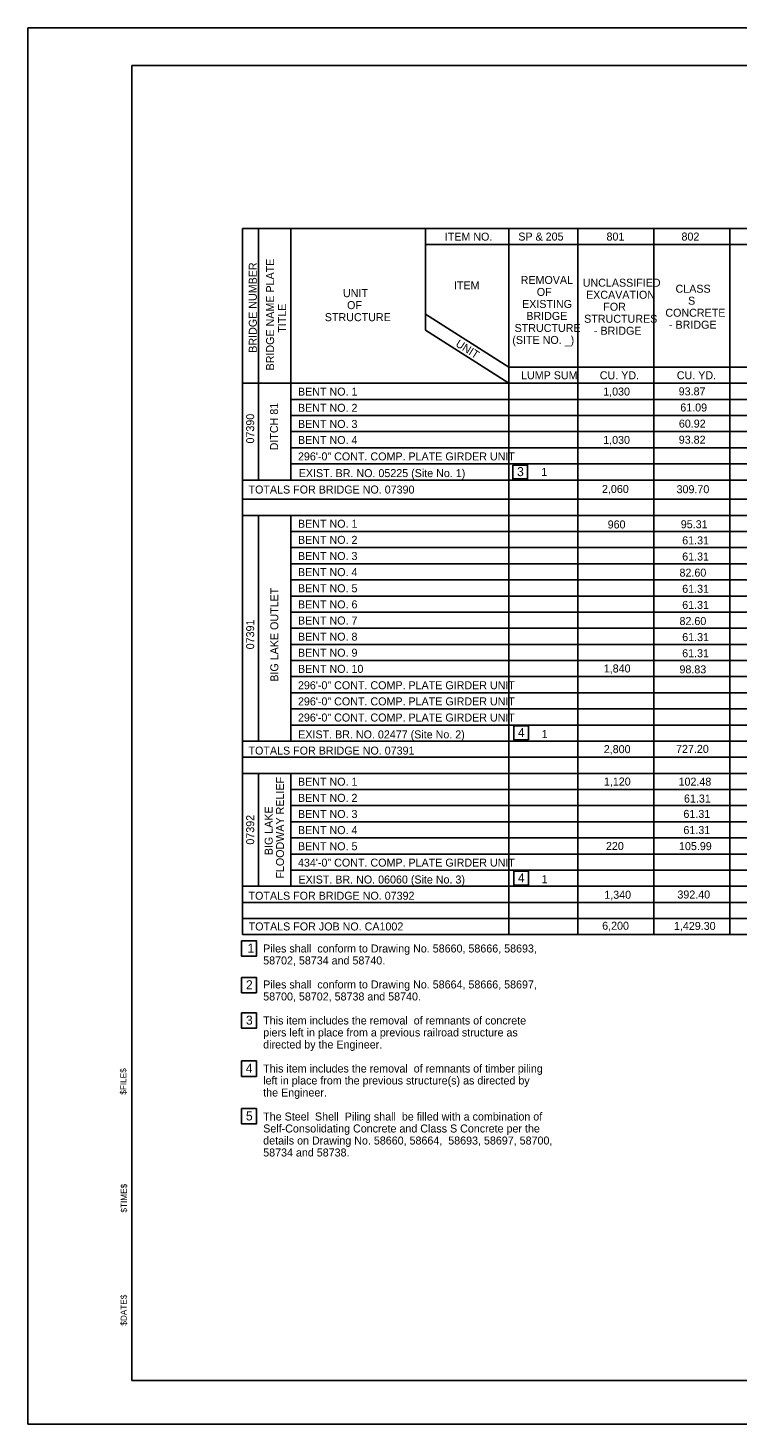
# Model space of a CAD drawing. Extents: x 117751.5 to 117785.6, y 28052.1 to 28074.
# Drawn here: x 117751.53 to 117762.6, y 28052.15 to 28073.96 of the extents above; entities that cross this region are included whole.
import ezdxf

# ---------------------------------------------------------------- set-up
doc = ezdxf.new("R2010")
doc.units = 0
for name, color, linetype in [('border', 7, 'Continuous'), ('Level 1', 7, 'Continuous'), ('Level 40', 7, 'Continuous'), ('Level 62', 7, 'Continuous')]:
    doc.layers.add(name, color=color, linetype=linetype)

msp = doc.modelspace()

# ---------------------------------------------------------------- linework, layer by layer
at = {"layer": 'border'}
for p, q in [((117753.15, 28073.371), (117785.161, 28073.371)), ((117753.15, 28052.826), (117753.15, 28073.371)), ((117785.161, 28052.826), (117753.15, 28052.826))]:
    msp.add_line(p, q, dxfattribs=at)
at = {"layer": 'Level 1'}
for p, q in [((117754.881, 28070.823), (117754.881, 28059.793)), ((117754.881, 28070.823), (117783.697, 28070.823)), ((117755.133, 28070.823), (117755.133, 28066.894)), ((117755.637, 28070.823), (117755.637, 28066.894)), ((117757.737, 28070.824), (117757.737, 28069.235)), ((117759.038, 28059.793), (117759.038, 28070.823)), ((117760.12, 28059.793), (117760.12, 28070.823)), ((117761.307, 28059.793), (117761.307, 28070.823)), ((117762.493, 28059.793), (117762.493, 28070.823)), ((117757.737, 28070.571), (117773.657, 28070.571)), ((117757.737, 28069.487), (117759.038, 28068.657)), ((117757.737, 28069.235), (117759.038, 28068.405)), ((117759.038, 28068.657), (117783.697, 28068.657)), ((117754.881, 28068.405), (117783.697, 28068.405)), ((117755.637, 28068.153), (117783.697, 28068.153)), ((117755.637, 28067.901), (117783.697, 28067.901)), ((117755.637, 28067.65), (117783.697, 28067.649)), ((117755.637, 28067.398), (117783.697, 28067.398)), ((117755.637, 28067.146), (117783.697, 28067.146)), ((117754.881, 28066.894), (117783.697, 28066.894)), ((117754.881, 28066.593), (117783.697, 28066.593)), ((117754.881, 28066.342), (117783.697, 28066.342)), ((117755.133, 28062.815), (117755.133, 28066.342)), ((117755.637, 28062.815), (117755.637, 28066.342)), ((117755.637, 28066.09), (117783.697, 28066.09)), ((117755.637, 28065.838), (117783.697, 28065.838)), ((117755.637, 28065.586), (117783.697, 28065.586)), ((117755.637, 28065.334), (117783.697, 28065.334)), ((117755.637, 28065.082), (117783.697, 28065.082)), ((117755.637, 28064.83), (117783.697, 28064.83)), ((117755.637, 28064.578), (117783.697, 28064.578)), ((117755.637, 28064.327), (117783.697, 28064.327)), ((117755.637, 28064.075), (117783.697, 28064.075)), ((117755.637, 28063.823), (117783.697, 28063.823)), ((117755.637, 28063.571), (117783.697, 28063.571)), ((117755.637, 28063.319), (117783.697, 28063.319)), ((117755.637, 28063.067), (117783.697, 28063.067)), ((117754.881, 28062.815), (117783.697, 28062.815)), ((117754.881, 28062.563), (117773.657, 28062.563)), ((117754.881, 28062.563), (117783.697, 28062.563)), ((117754.881, 28062.312), (117783.697, 28062.312)), ((117755.133, 28060.548), (117755.133, 28062.312)), ((117755.637, 28060.548), (117755.637, 28062.312)), ((117755.637, 28062.06), (117783.697, 28062.06)), ((117755.637, 28061.808), (117783.697, 28061.808)), ((117755.637, 28061.556), (117783.697, 28061.556)), ((117755.637, 28061.304), (117783.697, 28061.304)), ((117755.637, 28061.052), (117783.697, 28061.052)), ((117755.637, 28060.8), (117783.697, 28060.8)), ((117754.881, 28060.548), (117783.697, 28060.548)), ((117754.881, 28060.297), (117773.657, 28060.297)), ((117754.881, 28060.297), (117783.697, 28060.297)), ((117754.881, 28060.045), (117773.657, 28060.045)), ((117754.881, 28060.045), (117783.697, 28060.045)), ((117754.881, 28059.793), (117773.657, 28059.793)), ((117754.881, 28059.793), (117783.697, 28059.793))]:
    msp.add_line(p, q, dxfattribs=at)
at = {"layer": 'Level 40'}
for points in [[(117759.102, 28067.129), (117759.332, 28067.129), (117759.332, 28066.912), (117759.102, 28066.912)], [(117759.117, 28063.053), (117759.347, 28063.053), (117759.347, 28062.836), (117759.117, 28062.836)], [(117759.117, 28060.784), (117759.347, 28060.784), (117759.347, 28060.567), (117759.117, 28060.567)], [(117754.867, 28059.696), (117755.097, 28059.696), (117755.097, 28059.456), (117754.867, 28059.456)], [(117754.867, 28059.125), (117755.097, 28059.125), (117755.097, 28058.884), (117754.867, 28058.884)], [(117754.867, 28058.571), (117755.097, 28058.571), (117755.097, 28058.331), (117754.867, 28058.331)], [(117754.867, 28057.82), (117755.097, 28057.82), (117755.097, 28057.579), (117754.867, 28057.579)], [(117754.867, 28057.076), (117755.097, 28057.076), (117755.097, 28056.835), (117754.867, 28056.835)]]:
    msp.add_lwpolyline(points, close=True, dxfattribs=at)
at = {"layer": 'Level 62'}
msp.add_lwpolyline([(117751.53, 28073.957), (117785.648, 28073.957), (117785.648, 28052.147), (117751.53, 28052.147)], close=True, dxfattribs=at)

# ---------------------------------------------------------------- texts
at = {"layer": 'border'}
for s, p in [('$FILE$', (117753.067, 28057.292)), ('$TIME$', (117753.076, 28055.451)), ('$DATE$', (117753.073, 28053.684))]:
    msp.add_text(s, height=0.096, rotation=89.9999, dxfattribs=at).set_placement(p)
at = {"layer": 'Level 40'}
for s, height, p in [('ITEM NO.', 0.125, (117758.04, 28070.634)), ('SP & 205', 0.125, (117759.188, 28070.635)), ('801', 0.125, (117760.566, 28070.635)), ('802', 0.125, (117761.737, 28070.635)), ('REMOVAL', 0.125, (117759.225, 28069.957)), ('UNIT', 0.125, (117756.45, 28069.751)), ('ITEM', 0.125, (117758.183, 28069.873)), ('OF ', 0.125, (117759.477, 28069.77)), ('UNCLASSIFIED', 0.125, (117760.194, 28069.914)), ('EXCAVATION', 0.125, (117760.246, 28069.726)), ('CLASS', 0.125, (117761.644, 28069.82)), ('OF', 0.125, (117756.514, 28069.564)), ('EXISTING', 0.125, (117759.247, 28069.582)), ('FOR ', 0.125, (117760.515, 28069.539)), ('S', 0.125, (117761.839, 28069.633)), ('STRUCTURE', 0.125, (117756.166, 28069.376)), ('BRIDGE', 0.125, (117759.313, 28069.395)), ('STRUCTURES', 0.125, (117760.217, 28069.351)), ('CONCRETE', 0.125, (117761.485, 28069.445)), ('STRUCTURE', 0.125, (117759.13, 28069.207)), ('- BRIDGE', 0.125, (117760.369, 28069.164)), ('- BRIDGE', 0.125, (117761.541, 28069.258)), ('(SITE NO. _)', 0.125, (117759.095, 28069.02)), ('LUMP SUM', 0.125, (117759.231, 28068.468)), ('CU. YD.', 0.125, (117760.461, 28068.468)), ('CU. YD.', 0.125, (117761.664, 28068.468)), ('BENT NO. 1', 0.125, (117755.747, 28068.212)), ('1,030', 0.125, (117760.514, 28068.214)), ('93.87', 0.125, (117761.693, 28068.217)), ('BENT NO. 2', 0.125, (117755.747, 28067.96)), ('61.09', 0.125, (117761.718, 28067.965)), ('BENT NO. 3', 0.125, (117755.747, 28067.708)), ('60.92', 0.125, (117761.696, 28067.713)), ('BENT NO. 4', 0.125, (117755.747, 28067.457)), ('1,030', 0.125, (117760.514, 28067.458)), ('93.82', 0.125, (117761.694, 28067.462)), ('296\'-0" CONT. COMP. PLATE GIRDER UNIT', 0.125, (117755.747, 28067.201)), ('EXIST. BR. NO. 05225 (Site No. 1)', 0.125, (117755.759, 28066.94)), ('3', 0.141, (117759.169, 28066.955)), ('1', 0.125, (117759.547, 28066.958)), ('TOTALS FOR BRIDGE NO. 07390', 0.125, (117754.975, 28066.683)), ('2,060', 0.125, (117760.495, 28066.692)), ('309.70', 0.125, (117761.66, 28066.688)), ('BENT NO. 1', 0.125, (117755.747, 28066.149)), ('960', 0.125, (117760.584, 28066.138)), ('95.31', 0.125, (117761.726, 28066.141)), ('BENT NO. 2', 0.125, (117755.747, 28065.897)), ('61.31', 0.125, (117761.748, 28065.889)), ('BENT NO. 3', 0.125, (117755.747, 28065.645)), ('61.31', 0.125, (117761.748, 28065.637)), ('BENT NO. 4', 0.125, (117755.747, 28065.393)), ('82.60', 0.125, (117761.706, 28065.385)), ('BENT NO. 5', 0.125, (117755.747, 28065.141)), ('61.31', 0.125, (117761.748, 28065.133)), ('BENT NO. 6', 0.125, (117755.747, 28064.889)), ('61.31', 0.125, (117761.748, 28064.881)), ('BENT NO. 7', 0.125, (117755.747, 28064.637)), ('82.60', 0.125, (117761.706, 28064.629)), ('BENT NO. 8', 0.125, (117755.747, 28064.385)), ('61.31', 0.125, (117761.748, 28064.378)), ('BENT NO. 9', 0.125, (117755.747, 28064.134)), ('61.31', 0.125, (117761.748, 28064.126)), ('BENT NO. 10', 0.125, (117755.747, 28063.882)), ('1,840', 0.125, (117760.523, 28063.888)), ('98.83', 0.125, (117761.705, 28063.874)), ('296\'-0" CONT. COMP. PLATE GIRDER UNIT', 0.125, (117755.747, 28063.626)), ('296\'-0" CONT. COMP. PLATE GIRDER UNIT', 0.125, (117755.747, 28063.374)), ('296\'-0" CONT. COMP. PLATE GIRDER UNIT', 0.125, (117755.747, 28063.122)), ('EXIST. BR. NO. 02477 (Site No. 2)', 0.125, (117755.751, 28062.858)), ('4', 0.141, (117759.182, 28062.879)), ('1', 0.125, (117759.551, 28062.863)), ('TOTALS FOR BRIDGE NO. 07391', 0.125, (117754.975, 28062.605)), ('2,800', 0.125, (117760.523, 28062.628)), ('727.20', 0.125, (117761.652, 28062.632)), ('BENT NO. 1', 0.125, (117755.747, 28062.119)), ('1,120', 0.125, (117760.525, 28062.122)), ('102.48', 0.125, (117761.691, 28062.12)), ('BENT NO. 2', 0.125, (117755.747, 28061.867)), ('61.31', 0.125, (117761.776, 28061.856)), ('BENT NO. 3', 0.125, (117755.747, 28061.615)), ('61.31', 0.125, (117761.767, 28061.616)), ('BENT NO. 4', 0.125, (117755.747, 28061.363)), ('61.31', 0.125, (117761.767, 28061.364)), ('BENT NO. 5', 0.125, (117755.747, 28061.111)), ('220', 0.125, (117760.557, 28061.115)), ('105.99', 0.125, (117761.698, 28061.113)), ('434\'-0" CONT. COMP. PLATE GIRDER UNIT', 0.125, (117755.747, 28060.855)), ('EXIST. BR. NO. 06060 (Site No. 3)', 0.125, (117755.754, 28060.591)), ('4', 0.141, (117759.182, 28060.609)), ('1', 0.125, (117759.551, 28060.596)), ('TOTALS FOR BRIDGE NO. 07392', 0.125, (117754.975, 28060.338)), ('1,340', 0.125, (117760.531, 28060.353)), ('392.40', 0.125, (117761.673, 28060.357)), ('TOTALS FOR JOB NO. CA1002', 0.125, (117754.977, 28059.858)), ('6,200', 0.125, (117760.498, 28059.869)), ('1,429.30', 0.125, (117761.619, 28059.866)), ('1', 0.141, (117754.959, 28059.511)), ('Piles shall  conform to Drawing No. 58660, 58666, 58693, ', 0.125, (117755.204, 28059.514)), ('58702, 58734 and 58740.', 0.125, (117755.204, 28059.327)), ('2', 0.141, (117754.935, 28058.939)), ('Piles shall  conform to Drawing No. 58664, 58666, 58697, ', 0.125, (117755.204, 28058.952)), ('58700, 58702, 58738 and 58740.', 0.125, (117755.204, 28058.764)), ('3', 0.141, (117754.935, 28058.386)), ('This item includes the removal  of remnants of concrete ', 0.125, (117755.204, 28058.389)), ('piers left in place from a previous railroad structure as ', 0.125, (117755.204, 28058.202)), ('directed by the Engineer.', 0.125, (117755.204, 28058.014)), ('4', 0.141, (117754.932, 28057.634)), ('This item includes the removal  of remnants of timber piling ', 0.125, (117755.204, 28057.639)), ('left in place from the previous structure(s) as directed by ', 0.125, (117755.204, 28057.452)), ('the Engineer.', 0.125, (117755.204, 28057.264)), ('5', 0.141, (117754.935, 28056.89)), ('The Steel  Shell  Piling shall  be filled with a combination of ', 0.125, (117755.204, 28056.889)), ('Self-Consolidating Concrete and Class S Concrete per the ', 0.125, (117755.204, 28056.702)), ('details on Drawing No. 58660, 58664,  58693, 58697, 58700, ', 0.125, (117755.204, 28056.514)), ('58734 and 58738.', 0.125, (117755.204, 28056.327))]:
    msp.add_text(s, height=height, dxfattribs=at).set_placement(p)
for s, rotation, p in [('BRIDGE NUMBER', 90, (117755.104, 28068.883)), ('BRIDGE NAME PLATE', 90, (117755.374, 28068.606)), (' TITLE', 90, (117755.561, 28069.149)), ('UNIT', 327.4773, (117758.198, 28068.992)), ('DITCH 81', 90, (117755.436, 28067.358)), ('07390', 90, (117755.063, 28067.465)), ('BIG LAKE OUTLET', 90, (117755.44, 28063.744)), ('07391', 90, (117755.063, 28064.25)), ('FLOODWAY RELIEF', 90, (117755.529, 28060.668)), ('BIG LAKE', 90, (117755.352, 28061.034)), ('07392', 90, (117755.063, 28061.199))]:
    msp.add_text(s, height=0.125, rotation=rotation, dxfattribs=at).set_placement(p)

doc.saveas('drawing.dxf')
